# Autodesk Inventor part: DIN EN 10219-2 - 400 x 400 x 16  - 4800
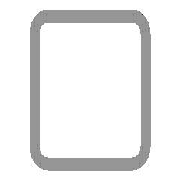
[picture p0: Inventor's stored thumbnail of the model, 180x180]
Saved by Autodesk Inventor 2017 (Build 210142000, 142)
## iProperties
IsCustomPart: 1
Created: 2016-02
Part Number: DIN EN 10219-2 - 400 x 400 x 16  - 4800
Material: Steel, Mild
Description: Cold formed welded structural hollow sections of non-alloy and fine grain structural steel
Document SubType Name: Modeling
Standard: DIN
Designer: iusti
Standard Revision: 2006-07
Standards Organization: DIN
Language: en-US
Size Designation: 400 x 400 x 16
Categories: <MemberInstance><Categories><Category DisplayName="Structural Shapes" InternalName="089c4875-fa83-4c05-b084-43b9cc11f5ed" Mnemonic="GRDR"><CategoryParameter Dis
Stock Number: 400 x 400 x 16
Density: 7.85 g/cm^3
Appearance: Semi-Polished
Mass: 884622 g
Surface Area: 141333 cm^2
Volume: 112691 cm^3
_CCFamilyMember: 142
_CCFamilyDisplayName: DIN EN 10219-2 (Square Hollow Section - Cold Formed) - Cold formed welded structural hollow sections of non-alloy and fine grain structural steel
_FrameMemberDoc: Frame Member File
_Version: 15.0.0
_GetPNFromCC: 1
G_L: 4800.000 mm
G_W: 400.000 mm
G_H: 400.000 mm
+0D5BCBA2-F1B2-4388-A824-2414ADB6311C+CUTDETAIL1: Cut
Author: iusti
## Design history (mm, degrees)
node "Start plane"
node "End plane"
sketch "Sketch"
  geometry: L1 (-200, -152)-(-200, 152); L2 (-152, 200)-(152, 200); L3 (200, 152)-(200, -152); L4 (152, -200)-(-152, -200); L5 (-152, 184)-(152, 184); L6 (184, 152)-(184, -152); L7 (152, -184)-(-152, -184); L8 (-184, -152)-(-184, 152); L9 (0, 293.918)-(0, -293.918) reference; L10 (-293.918, 0)-(293.918, 0) reference; A1 r 48 centre (-152, -152) between (-200, -152) and (-152, -200); A2 r 48 centre (-152, 152) between (-152, 200) and (-200, 152); A3 r 48 centre (152, 152) between (200, 152) and (152, 200); A4 r 48 centre (152, -152) between (152, -200) and (200, -152); A5 r 32 centre (-152, 152) between (-152, 184) and (-184, 152); A6 r 32 centre (152, 152) between (184, 152) and (152, 184); A7 r 32 centre (152, -152) between (152, -184) and (184, -152); A8 r 32 centre (-152, -152) between (-184, -152) and (-152, -184)
  constraints: 16 end point, 16 point on circle, 8 centre point, 8 tangent, 4 parallel, 3 equal radius, 2 perpendicular, 7 other
  dimensions: "d7" = 48 radius of A1 (= G_IR); "d10" = 400 distance between parallel lines of L2 L4 (= G_H); "d11" = 400 distance between parallel lines of L1 L3 (= G_W); "d12" = 16 distance between parallel lines of L3 L6 (= G_T); "d15" = 200 distance between parallel lines of L2 L10 (= 0.5 x d10); "d16" = 200 distance between parallel lines of L9 L3 (= 0.5 x d11)
extrude "Body" new body sketch "Sketch" stored distance "d3" = 4800 (= G_L); taper "d4" = 0 deg
node "Driven Length"
  sketch "Sketch3"
    geometry: L1 (0, 0)-(10, 0) reference
    constraints: 2 end point, 1 horizontal
  workplane "Work Plane3"
  sketch "Sketch4"
    geometry: L1 (-2, 200)-(12, 200) reference; L2 (-2, 5000)-(12, 5000) reference
    dimensions: "d18" = 4800 distance between parallel lines of L1 L2 (derived)
workplane "Work Plane4"
split "Split1"
body "Solid1"
other parameters: "G_W" = 400 [user parameter; used in 1 equation term], "G_H" = 400 [user parameter; used in 1 equation term], "G_T" = 16 [user parameter; used in 1 equation term], "G_IR" = 48 [user parameter; used in 1 equation term], "G_L" = 4800 (= d18) [user parameter; used in 1 equation term], "G_OFFSET_END" = 0 [user parameter; used in 1 equation term], "d17" = 90 deg
